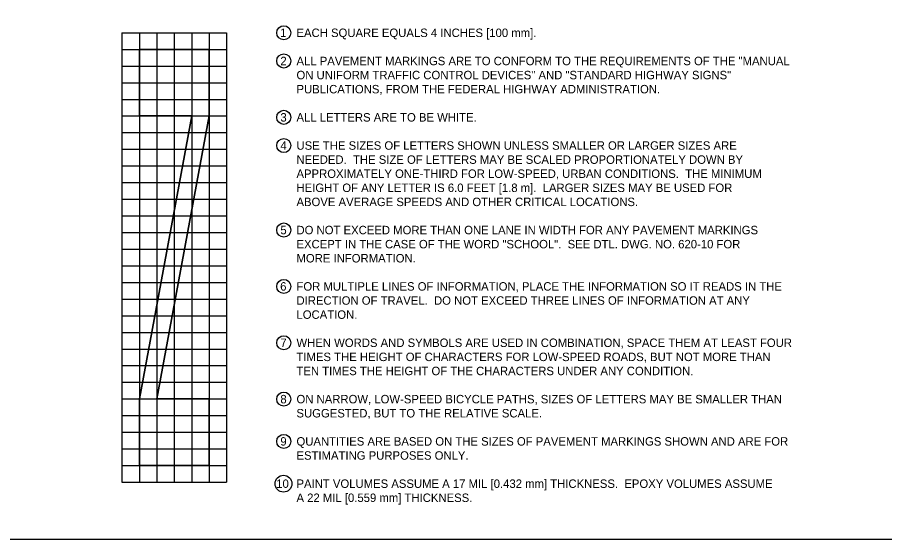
# Model space of a CAD drawing. Extents: x 49991.4 to 50021, y 49987.6 to 50011.4.
# Drawn here: x 50006.51 to 50012.67, y 49987.8 to 49991.51 of the extents above; entities that cross this region are included whole.
import ezdxf

# ---------------------------------------------------------------- set-up
doc = ezdxf.new("R2010")
doc.units = 0
for name, color, linetype in [('Level 1', 7, 'Continuous'), ('Level 2', 7, 'Continuous'), ('Level 9', 7, 'Continuous')]:
    doc.layers.add(name, color=color, linetype=linetype)

msp = doc.modelspace()

# ---------------------------------------------------------------- linework, layer by layer
at = {"layer": 'Level 1'}
for p, q in [((50007.3757, 49991.2782), (50007.8707, 49991.2782)), ((50007.3757, 49990.8057), (50007.3757, 49991.2782)), ((50007.8707, 49991.2782), (50007.3757, 49991.2782)), ((50007.3757, 49991.2782), (50007.3757, 49990.8057)), ((50007.8707, 49991.2782), (50007.3757, 49991.2782)), ((50007.3757, 49991.2782), (50007.3757, 49990.8057)), ((50007.8707, 49991.2782), (50007.8707, 49990.8057)), ((50007.8707, 49990.8057), (50007.8707, 49991.2782)), ((50007.8707, 49990.8057), (50007.8707, 49991.2782)), ((50007.3757, 49988.7976), (50007.747, 49990.8057)), ((50007.747, 49990.8057), (50007.3757, 49990.8057)), ((50007.3757, 49990.8057), (50007.747, 49990.8057)), ((50007.747, 49990.8057), (50007.3757, 49988.7976)), ((50007.3757, 49990.8057), (50007.747, 49990.8057)), ((50007.747, 49990.8057), (50007.3757, 49988.7976)), ((50007.8707, 49990.8057), (50007.4995, 49988.7976)), ((50007.4995, 49988.7976), (50007.8707, 49990.8057)), ((50007.4995, 49988.7976), (50007.8707, 49990.8057)), ((50007.3757, 49988.3251), (50007.3757, 49988.7976)), ((50007.3757, 49988.7976), (50007.3757, 49988.3251)), ((50007.3757, 49988.7976), (50007.3757, 49988.3251)), ((50007.4995, 49988.7976), (50007.8707, 49988.7976)), ((50007.8707, 49988.7976), (50007.4995, 49988.7976)), ((50007.8707, 49988.7976), (50007.4995, 49988.7976)), ((50007.8707, 49988.7976), (50007.8707, 49988.3251)), ((50007.8707, 49988.3251), (50007.8707, 49988.7976)), ((50007.8707, 49988.3251), (50007.8707, 49988.7976)), ((50007.8707, 49988.3251), (50007.3757, 49988.3251)), ((50007.3757, 49988.3251), (50007.8707, 49988.3251)), ((50007.3757, 49988.3251), (50007.8707, 49988.3251))]:
    msp.add_line(p, q, dxfattribs=at)
msp.add_lwpolyline([(49999.3835, 49998.9992), (50016.7501, 49998.9992), (50016.7501, 49987.7988), (49999.3835, 49987.7988)], close=True, dxfattribs=at)
at = {"layer": 'Level 2'}
for centre, radius in [((50008.4006, 49991.3961), 0.0501), ((50008.4006, 49991.1961), 0.0501), ((50008.4006, 49990.7961), 0.0501), ((50008.4006, 49990.5961), 0.0501), ((50008.4006, 49989.9961), 0.0501), ((50008.4006, 49989.5961), 0.0501), ((50008.4006, 49989.1961), 0.0501), ((50008.4006, 49988.7961), 0.0501), ((50008.4006, 49988.4961), 0.0501), ((50008.3983, 49988.1961), 0.0599)]:
    msp.add_circle(centre, radius, dxfattribs=at)
at = {"layer": 'Level 9'}
for p, q in [((50007.252, 49991.3963), (50007.9945, 49991.3963)), ((50007.252, 49991.3963), (50007.252, 49988.2069)), ((50007.3757, 49991.3963), (50007.3757, 49988.2069)), ((50007.4995, 49991.3963), (50007.4995, 49988.2069)), ((50007.6232, 49991.3963), (50007.6232, 49988.2069)), ((50007.747, 49991.3963), (50007.747, 49988.2069)), ((50007.8707, 49991.3963), (50007.8707, 49988.2069)), ((50007.9945, 49991.3963), (50007.9945, 49988.2069)), ((50007.252, 49991.2782), (50007.9945, 49991.2782)), ((50007.252, 49991.1601), (50007.9945, 49991.1601)), ((50007.252, 49991.0419), (50007.9945, 49991.0419)), ((50007.252, 49990.9238), (50007.9945, 49990.9238)), ((50007.252, 49990.8057), (50007.9945, 49990.8057)), ((50007.252, 49990.6876), (50007.9945, 49990.6876)), ((50007.252, 49990.5694), (50007.9945, 49990.5694)), ((50007.252, 49990.4513), (50007.9945, 49990.4513)), ((50007.252, 49990.3332), (50007.9945, 49990.3332)), ((50007.252, 49990.2151), (50007.9945, 49990.2151)), ((50007.252, 49990.0969), (50007.9945, 49990.0969)), ((50007.252, 49989.9788), (50007.9945, 49989.9788)), ((50007.252, 49989.8607), (50007.9945, 49989.8607)), ((50007.252, 49989.7426), (50007.9945, 49989.7426)), ((50007.252, 49989.6244), (50007.9945, 49989.6244)), ((50007.252, 49989.5063), (50007.9945, 49989.5063)), ((50007.252, 49989.3882), (50007.9945, 49989.3882)), ((50007.252, 49989.2701), (50007.9945, 49989.2701)), ((50007.252, 49989.1519), (50007.9945, 49989.1519)), ((50007.252, 49989.0338), (50007.9945, 49989.0338)), ((50007.252, 49988.9157), (50007.9945, 49988.9157)), ((50007.252, 49988.7976), (50007.9945, 49988.7976)), ((50007.252, 49988.6794), (50007.9945, 49988.6794)), ((50007.252, 49988.5613), (50007.9945, 49988.5613)), ((50007.252, 49988.4432), (50007.9945, 49988.4432)), ((50007.252, 49988.3251), (50007.9945, 49988.3251)), ((50007.252, 49988.2069), (50007.9945, 49988.2069))]:
    msp.add_line(p, q, dxfattribs=at)

# ---------------------------------------------------------------- texts
at = {"layer": 'Level 2'}
for s, p in [('EACH SQUARE EQUALS 4 INCHES [100 mm].', (50008.4907, 49991.3661)), ('1', (50008.3744, 49991.3662)), ('2', (50008.3766, 49991.1661)), ('ALL PAVEMENT MARKINGS ARE TO CONFORM TO THE REQUIREMENTS OF THE "MANUAL', (50008.4907, 49991.1661)), ('ON UNIFORM TRAFFIC CONTROL DEVICES" AND "STANDARD HIGHWAY SIGNS"', (50008.4907, 49991.0661)), ('PUBLICATIONS, FROM THE FEDERAL HIGHWAY ADMINISTRATION.', (50008.4907, 49990.9661)), ('3', (50008.3766, 49990.7661)), ('ALL LETTERS ARE TO BE WHITE.', (50008.4907, 49990.7661)), ('4', (50008.3766, 49990.5661)), ('USE THE SIZES OF LETTERS SHOWN UNLESS SMALLER OR LARGER SIZES ARE', (50008.4907, 49990.5661)), ('NEEDED.  THE SIZE OF LETTERS MAY BE SCALED PROPORTIONATELY DOWN BY', (50008.4907, 49990.4661)), ('APPROXIMATELY ONE-THIRD FOR LOW-SPEED, URBAN CONDITIONS.  THE MINIMUM', (50008.4907, 49990.3661)), ('HEIGHT OF ANY LETTER IS 6.0 FEET [1.8 m].  LARGER SIZES MAY BE USED FOR', (50008.4907, 49990.2661)), ('ABOVE AVERAGE SPEEDS AND OTHER CRITICAL LOCATIONS.', (50008.4907, 49990.1661)), ('5', (50008.3766, 49989.9661)), ('DO NOT EXCEED MORE THAN ONE LANE IN WIDTH FOR ANY PAVEMENT MARKINGS', (50008.4907, 49989.9661)), ('EXCEPT IN THE CASE OF THE WORD "SCHOOL".  SEE DTL. DWG. NO. 620-10 FOR', (50008.4907, 49989.8661)), ('MORE INFORMATION.', (50008.4907, 49989.7661)), ('6', (50008.375, 49989.5661)), ('FOR MULTIPLE LINES OF INFORMATION, PLACE THE INFORMATION SO IT READS IN THE', (50008.4907, 49989.5661)), ('DIRECTION OF TRAVEL.  DO NOT EXCEED THREE LINES OF INFORMATION AT ANY', (50008.4907, 49989.4661)), ('LOCATION.', (50008.4907, 49989.3661)), ('7', (50008.3766, 49989.1661)), ('WHEN WORDS AND SYMBOLS ARE USED IN COMBINATION, SPACE THEM AT LEAST FOUR', (50008.4907, 49989.1661)), ('TIMES THE HEIGHT OF CHARACTERS FOR LOW-SPEED ROADS, BUT NOT MORE THAN', (50008.4907, 49989.0661)), ('TEN TIMES THE HEIGHT OF THE CHARACTERS UNDER ANY CONDITION.', (50008.4907, 49988.9661)), ('8', (50008.3766, 49988.7661)), ('ON NARROW, LOW-SPEED BICYCLE PATHS, SIZES OF LETTERS MAY BE SMALLER THAN', (50008.4907, 49988.7661)), ('SUGGESTED, BUT TO THE RELATIVE SCALE.', (50008.4907, 49988.6661)), ('9', (50008.3764, 49988.4661)), ('QUANTITIES ARE BASED ON THE SIZES OF PAVEMENT MARKINGS SHOWN AND ARE FOR', (50008.4907, 49988.4661)), ('ESTIMATING PURPOSES ONLY.', (50008.4907, 49988.3661)), ('10', (50008.347, 49988.1661)), ('PAINT VOLUMES ASSUME A 17 MIL [0.432 mm] THICKNESS.  EPOXY VOLUMES ASSUME', (50008.4907, 49988.1661)), ('A 22 MIL [0.559 mm] THICKNESS.', (50008.4907, 49988.0661))]:
    msp.add_text(s, height=0.06, dxfattribs=at).set_placement(p)

doc.saveas('drawing.dxf')
